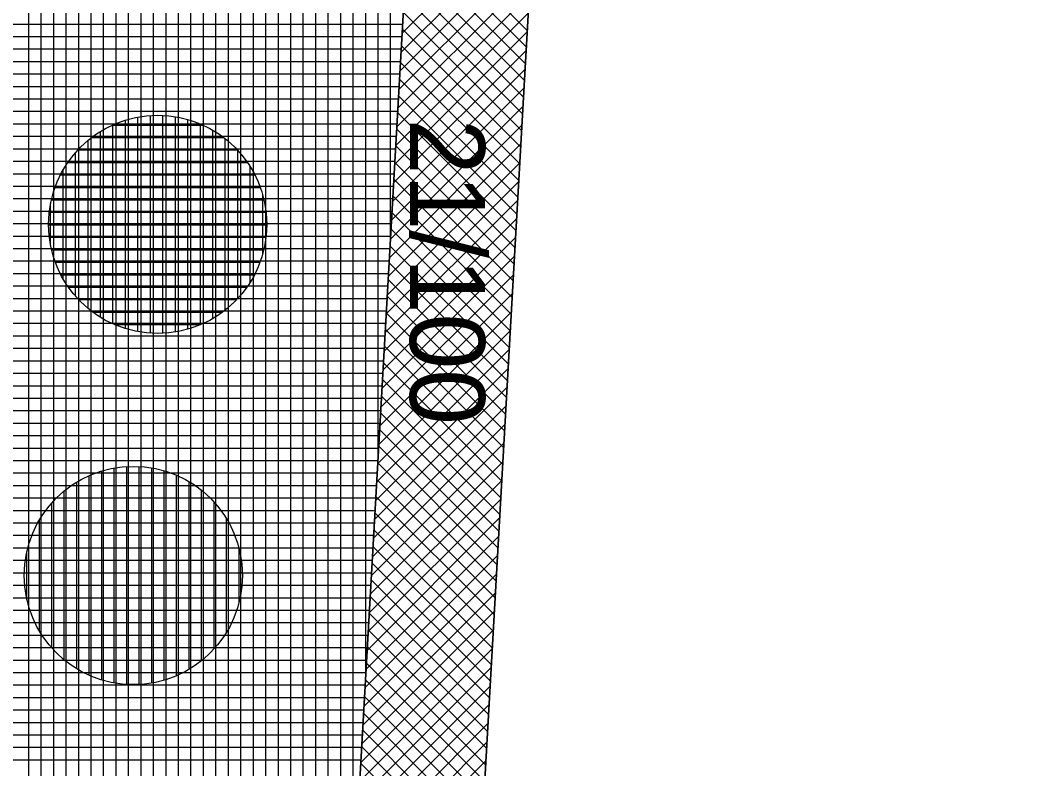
# Model space of a CAD drawing. Extents: x -565346 to -564154, y -1097386 to -1095620.
# Drawn here: x -564263.73 to -564247.53, y -1096638.73 to -1096626.73 of the extents above; entities that cross this region are included whole.
import ezdxf

# ---------------------------------------------------------------- set-up
doc = ezdxf.new("R2010")
doc.units = 0
for name, color, linetype in [('Vrstva 13', 7, 'Continuous'), ('Vrstva 40', 7, 'Continuous'), ('Vrstva 41', 7, 'Continuous'), ('Vrstva 42', 7, 'Continuous'), ('Vrstva 43', 7, 'Continuous'), ('Vrstva 44', 7, 'Continuous')]:
    doc.layers.add(name, color=color, linetype=linetype)

msp = doc.modelspace()

# ---------------------------------------------------------------- linework, layer by layer
at = {"layer": 'Vrstva 13'}
msp.add_line((-564252.76, -1096576.88), (-564261.08, -1096723.43), dxfattribs=at)
at = {"layer": 'Vrstva 41'}
msp.add_lwpolyline([(-564221.399, -1096446.296), (-564223.301, -1096445.676), (-564228.215, -1096460.758), (-564240.675, -1096505.018), (-564249.271, -1096529.938), (-564254.757, -1096576.767), (-564262.137, -1096706.758), (-564260.141, -1096706.872), (-564252.76, -1096576.88), (-564247.38, -1096530.59), (-564238.75, -1096505.56), (-564226.29, -1096461.3)], close=True, dxfattribs=at)
at = {"layer": 'Vrstva 42'}
for p, q in [((-564255.482, -1096624.815), (-564257.605, -1096626.939)), ((-564257.495, -1096624.997), (-564255.6, -1096626.893)), ((-564255.499, -1096625.115), (-564257.622, -1096627.239)), ((-564257.51, -1096625.265), (-564255.615, -1096627.16)), ((-564255.516, -1096625.415), (-564257.639, -1096627.539)), ((-564257.526, -1096625.532), (-564255.63, -1096627.428)), ((-564255.533, -1096625.715), (-564257.657, -1096627.839)), ((-564257.541, -1096625.8), (-564255.645, -1096627.695)), ((-564255.55, -1096626.015), (-564257.674, -1096628.139)), ((-564257.556, -1096626.068), (-564255.66, -1096627.963)), ((-564255.567, -1096626.315), (-564257.691, -1096628.439)), ((-564257.571, -1096626.335), (-564255.676, -1096628.231)), ((-564255.584, -1096626.615), (-564257.708, -1096628.738)), ((-564257.586, -1096626.603), (-564255.691, -1096628.498)), ((-564255.601, -1096626.915), (-564257.725, -1096629.038)), ((-564257.602, -1096626.87), (-564255.706, -1096628.766)), ((-564257.617, -1096627.138), (-564255.721, -1096629.034)), ((-564255.618, -1096627.214), (-564257.742, -1096629.338)), ((-564257.632, -1096627.406), (-564255.736, -1096629.301)), ((-564255.635, -1096627.514), (-564257.759, -1096629.638)), ((-564257.647, -1096627.673), (-564255.752, -1096629.569)), ((-564255.652, -1096627.814), (-564257.776, -1096629.938)), ((-564257.662, -1096627.941), (-564255.767, -1096629.837)), ((-564255.669, -1096628.114), (-564257.793, -1096630.238)), ((-564257.678, -1096628.209), (-564255.782, -1096630.104)), ((-564255.686, -1096628.414), (-564257.81, -1096630.538)), ((-564257.693, -1096628.476), (-564255.797, -1096630.372)), ((-564255.703, -1096628.714), (-564257.827, -1096630.838)), ((-564257.708, -1096628.744), (-564255.812, -1096630.64)), ((-564255.72, -1096629.014), (-564257.844, -1096631.137)), ((-564257.723, -1096629.012), (-564255.828, -1096630.907)), ((-564255.737, -1096629.313), (-564257.861, -1096631.437)), ((-564257.738, -1096629.279), (-564255.843, -1096631.175)), ((-564257.753, -1096629.547), (-564255.858, -1096631.443)), ((-564255.754, -1096629.613), (-564257.878, -1096631.737)), ((-564257.769, -1096629.815), (-564255.873, -1096631.71)), ((-564255.771, -1096629.913), (-564257.895, -1096632.037)), ((-564255.788, -1096630.213), (-564257.912, -1096632.337)), ((-564257.784, -1096630.082), (-564255.888, -1096631.978)), ((-564257.799, -1096630.35), (-564255.903, -1096632.245)), ((-564255.805, -1096630.513), (-564257.929, -1096632.637)), ((-564257.814, -1096630.618), (-564255.919, -1096632.513)), ((-564255.822, -1096630.813), (-564257.946, -1096632.937)), ((-564257.829, -1096630.885), (-564255.934, -1096632.781)), ((-564255.839, -1096631.113), (-564257.963, -1096633.236)), ((-564257.845, -1096631.153), (-564255.949, -1096633.048)), ((-564255.856, -1096631.413), (-564257.98, -1096633.536)), ((-564257.86, -1096631.42), (-564255.964, -1096633.316)), ((-564255.873, -1096631.712), (-564257.997, -1096633.836)), ((-564257.875, -1096631.688), (-564255.979, -1096633.584)), ((-564257.89, -1096631.956), (-564255.995, -1096633.851)), ((-564255.89, -1096632.012), (-564258.014, -1096634.136)), ((-564255.907, -1096632.312), (-564258.031, -1096634.436)), ((-564257.905, -1096632.223), (-564256.01, -1096634.119)), ((-564257.921, -1096632.491), (-564256.025, -1096634.387)), ((-564255.924, -1096632.612), (-564258.048, -1096634.736)), ((-564257.936, -1096632.759), (-564256.04, -1096634.654)), ((-564255.941, -1096632.912), (-564258.065, -1096635.036)), ((-564257.951, -1096633.026), (-564256.055, -1096634.922)), ((-564255.958, -1096633.212), (-564258.082, -1096635.336)), ((-564257.966, -1096633.294), (-564256.071, -1096635.19)), ((-564255.975, -1096633.512), (-564258.099, -1096635.635)), ((-564257.981, -1096633.562), (-564256.086, -1096635.457)), ((-564255.992, -1096633.812), (-564258.116, -1096635.935)), ((-564257.997, -1096633.829), (-564256.101, -1096635.725)), ((-564256.009, -1096634.111), (-564258.133, -1096636.235)), ((-564258.012, -1096634.097), (-564256.116, -1096635.993)), ((-564256.026, -1096634.411), (-564258.15, -1096636.535)), ((-564258.027, -1096634.365), (-564256.131, -1096636.26)), ((-564256.043, -1096634.711), (-564258.167, -1096636.835)), ((-564258.042, -1096634.632), (-564256.147, -1096636.528)), ((-564258.057, -1096634.9), (-564256.162, -1096636.795)), ((-564256.061, -1096635.011), (-564258.184, -1096637.135)), ((-564258.073, -1096635.168), (-564256.177, -1096637.063)), ((-564256.078, -1096635.311), (-564258.201, -1096637.435)), ((-564258.088, -1096635.435), (-564256.192, -1096637.331)), ((-564256.095, -1096635.611), (-564258.218, -1096637.734)), ((-564258.103, -1096635.703), (-564256.207, -1096637.598)), ((-564256.112, -1096635.911), (-564258.235, -1096638.034)), ((-564258.118, -1096635.97), (-564256.223, -1096637.866)), ((-564256.129, -1096636.21), (-564258.252, -1096638.334)), ((-564258.133, -1096636.238), (-564256.238, -1096638.134)), ((-564256.146, -1096636.51), (-564258.269, -1096638.634)), ((-564258.149, -1096636.506), (-564256.253, -1096638.401)), ((-564256.163, -1096636.81), (-564258.286, -1096638.934)), ((-564258.164, -1096636.773), (-564256.268, -1096638.669)), ((-564256.18, -1096637.11), (-564258.303, -1096639.234)), ((-564258.179, -1096637.041), (-564256.283, -1096638.937)), ((-564258.194, -1096637.309), (-564256.299, -1096639.204)), ((-564256.197, -1096637.41), (-564258.32, -1096639.534)), ((-564258.209, -1096637.576), (-564256.314, -1096639.472)), ((-564256.214, -1096637.71), (-564258.337, -1096639.834)), ((-564258.225, -1096637.844), (-564256.329, -1096639.74)), ((-564256.231, -1096638.01), (-564258.355, -1096640.133)), ((-564258.24, -1096638.112), (-564256.344, -1096640.007)), ((-564256.248, -1096638.31), (-564258.372, -1096640.433)), ((-564258.255, -1096638.379), (-564256.359, -1096640.275)), ((-564256.265, -1096638.609), (-564258.389, -1096640.733)), ((-564258.27, -1096638.647), (-564256.375, -1096640.543))]:
    msp.add_line(p, q, dxfattribs=at)
at = {"layer": 'Vrstva 43'}
for p, q in [((-564257.79, -1096630.19), (-564257.79, -1096537.878)), ((-564257.99, -1096633.713), (-564257.99, -1096539.599)), ((-564258.19, -1096637.236), (-564258.19, -1096541.32)), ((-564258.39, -1096640.759), (-564258.39, -1096543.04)), ((-564258.59, -1096644.281), (-564258.59, -1096544.761)), ((-564258.79, -1096647.804), (-564258.79, -1096546.482)), ((-564258.99, -1096651.327), (-564258.99, -1096548.203)), ((-564259.19, -1096654.85), (-564259.19, -1096549.923)), ((-564259.39, -1096658.372), (-564259.39, -1096551.644)), ((-564259.59, -1096661.895), (-564259.59, -1096553.365)), ((-564259.79, -1096665.418), (-564259.79, -1096555.085)), ((-564259.99, -1096668.941), (-564259.99, -1096556.806)), ((-564260.19, -1096672.464), (-564260.19, -1096558.527)), ((-564260.39, -1096675.986), (-564260.39, -1096560.248)), ((-564260.59, -1096679.509), (-564260.59, -1096561.968)), ((-564260.79, -1096683.032), (-564260.79, -1096563.689)), ((-564260.99, -1096686.555), (-564260.99, -1096565.41)), ((-564261.19, -1096690.078), (-564261.19, -1096567.13)), ((-564261.39, -1096693.6), (-564261.39, -1096568.851)), ((-564261.59, -1096697.123), (-564261.59, -1096570.572)), ((-564261.79, -1096700.646), (-564261.79, -1096572.293)), ((-564261.99, -1096704.169), (-564261.99, -1096574.013)), ((-564262.19, -1096726.788), (-564262.19, -1096575.734)), ((-564262.39, -1096726.776), (-564262.39, -1096578.915)), ((-564262.59, -1096726.765), (-564262.59, -1096582.438)), ((-564262.79, -1096726.753), (-564262.79, -1096585.961)), ((-564262.99, -1096726.742), (-564262.99, -1096589.485)), ((-564263.19, -1096726.731), (-564263.19, -1096593.008)), ((-564263.39, -1096728.822), (-564263.39, -1096596.531)), ((-564263.59, -1096732.346), (-564263.59, -1096600.055)), ((-564265.108, -1096626.79), (-564257.597, -1096626.79)), ((-564265.119, -1096626.99), (-564257.608, -1096626.99)), ((-564265.13, -1096627.19), (-564257.62, -1096627.19)), ((-564265.142, -1096627.39), (-564257.631, -1096627.39)), ((-564265.153, -1096627.59), (-564257.642, -1096627.59)), ((-564265.164, -1096627.79), (-564257.654, -1096627.79)), ((-564265.176, -1096627.99), (-564257.665, -1096627.99)), ((-564265.187, -1096628.19), (-564257.676, -1096628.19)), ((-564265.198, -1096628.39), (-564257.688, -1096628.39)), ((-564265.21, -1096628.59), (-564257.699, -1096628.59)), ((-564265.221, -1096628.79), (-564257.711, -1096628.79)), ((-564265.233, -1096628.99), (-564257.722, -1096628.99)), ((-564265.244, -1096629.19), (-564257.733, -1096629.19)), ((-564265.255, -1096629.39), (-564257.745, -1096629.39)), ((-564265.267, -1096629.59), (-564257.756, -1096629.59)), ((-564265.278, -1096629.79), (-564257.767, -1096629.79)), ((-564265.289, -1096629.99), (-564257.779, -1096629.99)), ((-564265.301, -1096630.19), (-564257.79, -1096630.19)), ((-564265.312, -1096630.39), (-564257.801, -1096630.39)), ((-564265.323, -1096630.59), (-564257.813, -1096630.59)), ((-564265.335, -1096630.79), (-564257.824, -1096630.79)), ((-564265.346, -1096630.99), (-564257.835, -1096630.99)), ((-564265.357, -1096631.19), (-564257.847, -1096631.19)), ((-564265.369, -1096631.39), (-564257.858, -1096631.39)), ((-564265.38, -1096631.59), (-564257.869, -1096631.59)), ((-564265.391, -1096631.79), (-564257.881, -1096631.79)), ((-564265.403, -1096631.99), (-564257.892, -1096631.99)), ((-564265.414, -1096632.19), (-564257.904, -1096632.19)), ((-564265.426, -1096632.39), (-564257.915, -1096632.39)), ((-564265.437, -1096632.59), (-564257.926, -1096632.59)), ((-564265.448, -1096632.79), (-564257.938, -1096632.79)), ((-564265.46, -1096632.99), (-564257.949, -1096632.99)), ((-564265.471, -1096633.19), (-564257.96, -1096633.19)), ((-564265.482, -1096633.39), (-564257.972, -1096633.39)), ((-564265.494, -1096633.59), (-564257.983, -1096633.59)), ((-564265.505, -1096633.79), (-564257.994, -1096633.79)), ((-564265.516, -1096633.99), (-564258.006, -1096633.99)), ((-564265.528, -1096634.19), (-564258.017, -1096634.19)), ((-564265.539, -1096634.39), (-564258.028, -1096634.39)), ((-564265.55, -1096634.59), (-564258.04, -1096634.59)), ((-564265.562, -1096634.79), (-564258.051, -1096634.79)), ((-564265.573, -1096634.99), (-564258.063, -1096634.99)), ((-564265.584, -1096635.19), (-564258.074, -1096635.19)), ((-564265.596, -1096635.39), (-564258.085, -1096635.39)), ((-564265.607, -1096635.59), (-564258.097, -1096635.59)), ((-564265.619, -1096635.79), (-564258.108, -1096635.79)), ((-564265.63, -1096635.99), (-564258.119, -1096635.99)), ((-564265.641, -1096636.19), (-564258.131, -1096636.19)), ((-564265.653, -1096636.39), (-564258.142, -1096636.39)), ((-564265.664, -1096636.59), (-564258.153, -1096636.59)), ((-564265.675, -1096636.79), (-564258.165, -1096636.79)), ((-564265.687, -1096636.99), (-564258.176, -1096636.99)), ((-564265.698, -1096637.19), (-564258.187, -1096637.19)), ((-564265.709, -1096637.39), (-564258.199, -1096637.39)), ((-564265.721, -1096637.59), (-564258.21, -1096637.59)), ((-564265.732, -1096637.79), (-564258.221, -1096637.79)), ((-564265.743, -1096637.99), (-564258.233, -1096637.99)), ((-564265.755, -1096638.19), (-564258.244, -1096638.19)), ((-564265.766, -1096638.39), (-564258.256, -1096638.39)), ((-564265.777, -1096638.59), (-564258.267, -1096638.59))]:
    msp.add_line(p, q, dxfattribs=at)
msp.add_lwpolyline([(-564261.274, -1096726.84), (-564260.141, -1096706.872), (-564262.137, -1096706.758), (-564254.757, -1096576.767), (-564249.271, -1096529.938), (-564240.675, -1096505.018), (-564228.215, -1096460.758), (-564223.301, -1096445.676), (-564221.399, -1096446.296), (-564218.92, -1096438.69), (-564229.82, -1096442.05), (-564230.6, -1096442.93), (-564256.683, -1096528.354), (-564262.228, -1096576.061), (-564269.623, -1096706.334), (-564272.07, -1096706.16), (-564273.28, -1096725.96)], dxfattribs=at)
at = {"layer": 'Vrstva 44'}
for p, q in [((-564261.84, -1096631.723), (-564261.84, -1096628.283)), ((-564261.64, -1096631.748), (-564261.64, -1096628.259)), ((-564261.44, -1096631.751), (-564261.44, -1096628.258)), ((-564261.24, -1096631.731), (-564261.24, -1096628.279)), ((-564262.242, -1096628.41), (-564260.806, -1096628.41)), ((-564262.24, -1096631.599), (-564262.24, -1096628.409)), ((-564262.04, -1096631.675), (-564262.04, -1096628.333)), ((-564261.04, -1096631.684), (-564261.04, -1096628.324)), ((-564260.84, -1096631.613), (-564260.84, -1096628.394)), ((-564262.44, -1096631.494), (-564262.44, -1096628.514)), ((-564260.64, -1096631.513), (-564260.64, -1096628.496)), ((-564262.64, -1096631.35), (-564262.64, -1096628.658)), ((-564262.581, -1096628.61), (-564260.469, -1096628.61)), ((-564260.44, -1096631.376), (-564260.44, -1096628.632)), ((-564262.84, -1096631.157), (-564262.84, -1096628.851)), ((-564262.801, -1096628.81), (-564260.247, -1096628.81)), ((-564260.24, -1096631.192), (-564260.24, -1096628.818)), ((-564262.963, -1096629.01), (-564260.084, -1096629.01)), ((-564260.04, -1096630.93), (-564260.04, -1096629.081)), ((-564263.082, -1096629.21), (-564259.967, -1096629.21)), ((-564263.04, -1096630.878), (-564263.04, -1096629.131)), ((-564263.17, -1096629.41), (-564259.88, -1096629.41)), ((-564259.84, -1096630.476), (-564259.84, -1096629.536)), ((-564263.24, -1096630.338), (-564263.24, -1096629.67)), ((-564263.228, -1096629.61), (-564259.82, -1096629.61)), ((-564263.261, -1096629.81), (-564259.786, -1096629.81)), ((-564263.272, -1096630.01), (-564259.776, -1096630.01)), ((-564263.261, -1096630.21), (-564259.788, -1096630.21)), ((-564263.226, -1096630.41), (-564259.824, -1096630.41)), ((-564263.164, -1096630.61), (-564259.883, -1096630.61)), ((-564263.075, -1096630.81), (-564259.973, -1096630.81)), ((-564262.956, -1096631.01), (-564260.094, -1096631.01)), ((-564262.79, -1096631.21), (-564260.258, -1096631.21)), ((-564262.563, -1096631.41), (-564260.483, -1096631.41)), ((-564262.216, -1096631.61), (-564260.834, -1096631.61)), ((-564262.22, -1096637.355), (-564262.22, -1096633.911)), ((-564262.02, -1096637.379), (-564262.02, -1096633.889)), ((-564261.82, -1096637.38), (-564261.82, -1096633.888)), ((-564261.62, -1096637.359), (-564261.62, -1096633.911)), ((-564262.62, -1096637.233), (-564262.62, -1096634.035)), ((-564262.51, -1096633.99), (-564261.32, -1096633.99)), ((-564262.42, -1096637.309), (-564262.42, -1096633.96)), ((-564261.42, -1096637.311), (-564261.42, -1096633.956)), ((-564261.22, -1096637.238), (-564261.22, -1096634.029)), ((-564262.899, -1096634.19), (-564260.927, -1096634.19)), ((-564262.82, -1096637.129), (-564262.82, -1096634.138)), ((-564261.02, -1096637.138), (-564261.02, -1096634.132)), ((-564260.82, -1096636.997), (-564260.82, -1096634.269)), ((-564263.143, -1096634.39), (-564260.683, -1096634.39)), ((-564263.02, -1096636.989), (-564263.02, -1096634.28)), ((-564263.318, -1096634.59), (-564260.512, -1096634.59)), ((-564263.22, -1096636.797), (-564263.22, -1096634.469)), ((-564260.62, -1096636.812), (-564260.62, -1096634.459)), ((-564263.42, -1096636.524), (-564263.42, -1096634.743)), ((-564260.42, -1096636.545), (-564260.42, -1096634.727)), ((-564263.445, -1096634.79), (-564260.381, -1096634.79)), ((-564263.539, -1096634.99), (-564260.289, -1096634.99)), ((-564263.606, -1096635.19), (-564260.223, -1096635.19)), ((-564260.22, -1096636.07), (-564260.22, -1096635.203)), ((-564263.646, -1096635.39), (-564260.182, -1096635.39)), ((-564263.62, -1096636.022), (-564263.62, -1096635.25)), ((-564263.662, -1096635.59), (-564260.165, -1096635.59)), ((-564263.655, -1096635.79), (-564260.172, -1096635.79)), ((-564263.626, -1096635.99), (-564260.203, -1096635.99)), ((-564263.573, -1096636.19), (-564260.257, -1096636.19)), ((-564263.491, -1096636.39), (-564260.336, -1096636.39)), ((-564263.378, -1096636.59), (-564260.45, -1096636.59)), ((-564263.227, -1096636.79), (-564260.602, -1096636.79)), ((-564263.019, -1096636.99), (-564260.811, -1096636.99)), ((-564262.715, -1096637.19), (-564261.117, -1096637.19))]:
    msp.add_line(p, q, dxfattribs=at)
for centre in [(-564261.524, -1096630.004), (-564261.914, -1096635.634)]:
    msp.add_circle(centre, 1.75, dxfattribs=at)

# ---------------------------------------------------------------- texts
at = {"layer": 'Vrstva 40'}
msp.add_text('21/100', height=1.2, rotation=270, dxfattribs=at).set_placement((-564257.48, -1096628.31))

doc.saveas('drawing.dxf')
